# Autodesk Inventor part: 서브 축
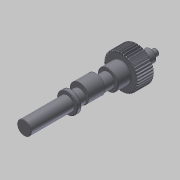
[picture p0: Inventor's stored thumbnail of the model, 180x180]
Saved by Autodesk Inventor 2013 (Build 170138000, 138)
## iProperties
Created: 2016-02
Part Number: 서브 축
Material: 강철, 연강
Document SubType Name: Modeling
Designer: mdu
Categories: <?xml version="1.0" encoding="UTF-16"?> <MemberInstance><Categories><FamilyTemplate><FamilyTemplateParameter ValueType="xs:double" Id="1" ObjectReferenceKey="da
Density: 7.86 g/cm^3
Mass: 506.173 g
Surface Area: 164.116 cm^2
Volume: 64.3986 cm^3
CustomPartVersion: 1
Author: mdu
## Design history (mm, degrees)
sketch "Sketch1"
  geometry: C1 r 21 at (0, 0)
  constraints: 1 centre point
  dimensions: "d0" = 42 diameter of C1 (= da_da)
extrude "Extrusion1" new body sketch "Sketch1" distance "d1" = 20 (= da_b); taper "d2" = 0 deg
workplane "Work Plane2"
feature "피치 지름" dims "d4" = 10, "d5" = 0
workplane "Work Plane8"
workplane "Work Plane9"
chamfer "모따기1" distance "d49" = 1; stored, may be unused: second distance "d50" = 2, angle "d51" = 45 deg
sketch "스케치3"
  geometry: C1 r 12.5 at (0, 0); 1 further point
  constraints: 1 centre point, 1 coincident
  dimensions: "d52" = 25 diameter of C1
extrude "돌출2" join sketch "스케치3" distance "d53" = 16; taper "d54" = 0 deg
sketch "스케치4"
  geometry: C1 r 8.5 at (0, 0); 1 further point
  constraints: 1 centre point, 1 coincident
  dimensions: "d55" = 17 diameter of C1
extrude "돌출3" join sketch "스케치4" distance "d56" = 103; taper "d57" = 0 deg
sketch "스케치5"
  geometry: C1 r 7.5 at (0, 0); 1 further point
  constraints: 1 centre point, 1 coincident
  dimensions: "d62" = 15 diameter of C1
extrude "돌출4" join sketch "스케치5" distance "d63" = 16; taper "d64" = 0 deg
sketch "스케치6"
  geometry: C1 r 4 at (0, 0); 1 further point
  constraints: 1 centre point, 1 coincident
  dimensions: "d65" = 8 diameter of C1
extrude "돌출5" join sketch "스케치6" distance "d66" = 7; taper "d67" = 0 deg
chamfer "모따기2" distance "d58" = 0.5; stored, may be unused: second distance "d59" = 2, angle "d60" = 45 deg
fillet "모깎기1" dims "d61" = 0.5
feature "스퍼 기어" dims "da_b" = 20, "da_d" = 40, "da_aw" = 31, "da_da" = 42, "da_df" = 37.5, "da_dw" = 40, angle "da_beta" = 0 deg, "da_lefttooth" = 0, "da_righttooth" = 0
node "작업 평면11"
sketch "스케치7"
  geometry: C1 r 8.5 at (0, 0) reference; C2 r 11.5 at (0, 3); 1 further point
  constraints: 1 centre point, 1 tangent, 1 vertical alignment
  dimensions: "d71" = 3 distance of C2.centre point (0, 0); "d72" = 23 diameter of C2 (derived)
extrude "돌출6" join sketch "스케치7" stored distance "d73" = 20; taper "d74" = 0 deg
node "작업 평면12"
sketch "스케치8"
  geometry: C1 r 12.5 at (0, 0) reference; 1 further point
extrude "돌출7" join sketch "스케치8" distance "d76" = 5; taper "d77" = 0 deg
chamfer "모따기3" distance "d78" = 0.5; stored, may be unused: second distance "d79" = 2, angle "d80" = 45 deg
body "Solid1"
sketch "Sketch2"
  geometry: C1 r 21 at (0, 0) reference; C2 r 20 at (0, 0)
  constraints: 1 centre point, 1 coincident
  dimensions: "d3" = 40 diameter of C2 (= da_dw)
body "Srf1"
other parameters: "d16" = 31 (= da_aw), "d17" = 0, "d34" = 4.5 deg (computed from da_z), "d39" = 0, "d41" = 0, "d43" = 31 (= da_aw), "d46" = 31 (= da_aw), "d47" = 0, "d48" = 0, "d68" = 25
